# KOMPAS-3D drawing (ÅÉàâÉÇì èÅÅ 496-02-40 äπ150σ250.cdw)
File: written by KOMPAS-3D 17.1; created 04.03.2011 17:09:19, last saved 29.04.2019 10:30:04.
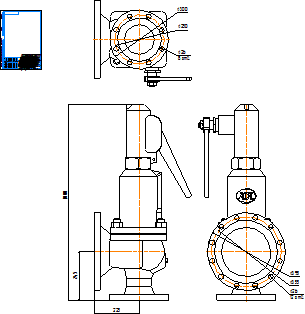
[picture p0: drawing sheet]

Sheet 1: A4, portrait

Title block, sheet 1: name: ПРЕГРАН КПП 496-02-40 / Ду150х250; material: Внимание! Данный продукт является объектом авторского права ООО «Торговый Дом АДЛ». / Запрещается изменение, копирование, распространение / (в том числе путем копирования на другие сайты и ресурсы в Интернете) / или любое иное использование информации и объектов без предварительного / согласия правообладателя (ООО «Торговый Дом АДЛ»).; scale: 1:1; sheets: 1; organisation: ООО "Торговый дом АДЛ"; sheet format: A4; stored path: C:\Users\tra\Desktop\2д чертежи\Предохранительные клапаны ПРЕГРАН\ПРЕГРАН 496\ПРЕГРАН КПП 496-02-40\KOMPAS 2D\ПРЕГРАН КПП 496-02-40 Ду150х250.cdw

Views: Спереди 4, Проекционный вид 6, Проекционный вид 7
Dimensions and other numbers on the sheet: 225; 245; 1000; 395; 355; 26; 12 отв.; 300; 250; 8 отв.; 1:1; 1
